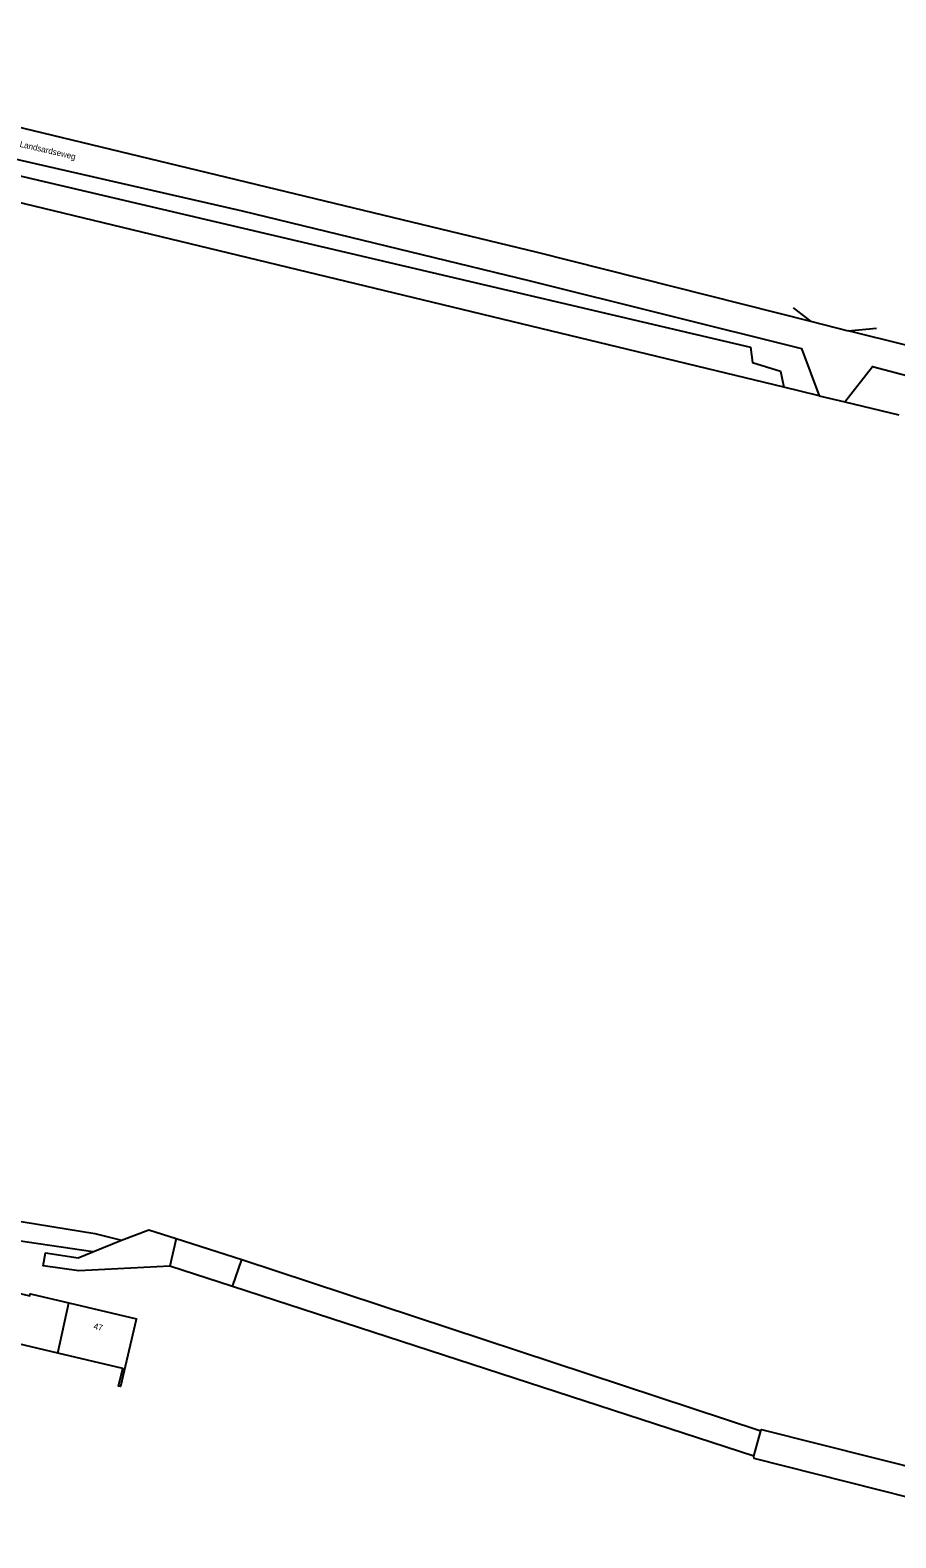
# Model space of a CAD drawing. Extents: x 152881 to 155736, y 382924 to 386919.
# Drawn here: x 154140.3 to 154283.4, y 385925 to 386174.3 of the extents above; entities that cross this region are included whole.
import ezdxf

# ---------------------------------------------------------------- set-up
doc = ezdxf.new("R2010")
doc.units = 0
for name, color, linetype in [('IMGEO_Berm_groen', 7, 'Continuous'), ('IMGEO_Gemengd_bos', 7, 'Continuous'), ('IMGEO_Groenvoorziening', 7, 'Continuous'), ('IMGEO_Hek', 7, 'Continuous'), ('IMGEO_Openbare_ruimte_label', 7, 'Continuous'), ('IMGEO_Pand', 7, 'Continuous'), ('IMGEO_Pand_nummerreeks', 7, 'Continuous'), ('IMGEO_Rijbaan_lokaal_gesloten', 7, 'Continuous'), ('IMGEO_Rijbaan_lokaal_halfverhard', 7, 'Continuous'), ('IMGEO_Rijbaan_lokaal_open', 7, 'Continuous')]:
    doc.layers.add(name, color=color, linetype=linetype)

msp = doc.modelspace()

# ---------------------------------------------------------------- linework, layer by layer
at = {"layer": 'IMGEO_Berm_groen'}
msp.add_lwpolyline([(154274.93, 386112.85), (154283.85, 386110.7)], dxfattribs=at)
at = {"layer": 'IMGEO_Gemengd_bos'}
for points in [[(154033.83, 386134.76), (154047.83, 386149.98), (154055.73, 386165.2), (154056.16, 386165.86), (154056.69, 386166.45), (154057.3, 386166.96), (154057.98, 386167.36), (154058.71, 386167.66), (154059.92, 386167.9), (154127.3, 386152.88), (154259.36, 386121.88), (154259.71, 386119.35), (154264.33, 386117.92), (154264.88, 386115.29)], [(154264.88, 386115.29), (154062.18, 386164.23), (154057.46, 386165.37), (154048.47, 386132.65), (154038.47, 386128.14)]]:
    msp.add_lwpolyline(points, dxfattribs=at)
at = {"layer": 'IMGEO_Groenvoorziening'}
for points in [[(154266.41, 386128.41), (154269.29, 386126.19)], [(154275.49, 386124.62), (154280.19, 386125.06)], [(154270.73, 386113.87), (154264.88, 386115.29)]]:
    msp.add_lwpolyline(points, dxfattribs=at)
at = {"layer": 'IMGEO_Hek'}
msp.add_lwpolyline([(154164.45, 385974.54), (154163.41, 385969.97)], dxfattribs=at)
at = {"layer": 'IMGEO_Pand'}
for points in [[(154144.86, 385955.57), (154138.4, 385957.1), (154138.46, 385957.34), (154126.96, 385960.07), (154128.11, 385964.85), (154128.94, 385968.34), (154129.35, 385968.26), (154129.23, 385967.65), (154140.25, 385965.04), (154140.32, 385965.39), (154140.59, 385965.33), (154146.72, 385963.88)], [(154146.72, 385963.88), (154157.86, 385961.26), (154157.83, 385961.14), (154155.22, 385950.04), (154154.93, 385950.11), (154155.61, 385953.03), (154144.86, 385955.57)], [(154144.86, 385955.57), (154146.72, 385963.88)]]:
    msp.add_lwpolyline(points, dxfattribs=at)
at = {"layer": 'IMGEO_Rijbaan_lokaal_gesloten'}
for points in [[(154088.55, 385992.5), (154127.33, 385979.3), (154129.62, 385978.83), (154151.01, 385975.37), (154155.39, 385974.23)], [(154150.69, 385972.31), (154129.28, 385975.47), (154126.33, 385976.28), (154121.26, 385978.08)], [(154150.69, 385972.31), (154155.39, 385974.23)]]:
    msp.add_lwpolyline(points, dxfattribs=at)
at = {"layer": 'IMGEO_Rijbaan_lokaal_halfverhard'}
for points in [[(153787.73, 386243.9), (153832.39, 386229.81), (153861.29, 386221.97), (153898.8, 386212.97), (153911.96, 386210.24), (153966.93, 386196.58), (153980.85, 386192.92), (153991.44, 386190.83), (154000, 386188.89), (154053.94, 386176.66), (154067.49, 386174.38), (154093.57, 386168.66), (154129.58, 386160.43), (154224.08, 386137.58), (154269.29, 386126.19)], [(154062.51, 386169.86), (154062.81, 386169.79), (154128.09, 386155.22), (154175.35, 386144.46), (154222.94, 386132.87), (154267.81, 386121.67), (154270.73, 386113.87)], [(154269.29, 386126.19), (154275.49, 386124.62)], [(154348.81, 386105.67), (154285.28, 386122.16), (154275.49, 386124.62)], [(154274.93, 386112.85), (154279.53, 386118.71), (154347.48, 386100.73), (154408.56, 386087.31), (154423.72, 386083.48), (154433.26, 386079.82)], [(154270.73, 386113.87), (154274.93, 386112.85)]]:
    msp.add_lwpolyline(points, dxfattribs=at)
at = {"layer": 'IMGEO_Rijbaan_lokaal_open'}
for points in [[(154155.39, 385974.23), (154159.91, 385975.98), (154164.45, 385974.54)], [(154163.41, 385969.97), (154148.33, 385969.16), (154142.44, 385970.02), (154142.85, 385972.13), (154148.24, 385971.33), (154150.69, 385972.31)], [(154164.45, 385974.54), (154163.41, 385969.97)], [(154164.45, 385974.54), (154175.28, 385971.08)], [(154173.77, 385966.59), (154163.41, 385969.97)], [(154173.77, 385966.59), (154175.28, 385971.08)], [(154175.28, 385971.08), (154261.09, 385942.7)], [(154259.92, 385938.51), (154173.77, 385966.59)], [(154259.92, 385938.51), (154261.09, 385942.7)], [(154261.09, 385942.7), (154261.16, 385942.95), (154307.85, 385931.18), (154311.09, 385928.75)], [(154308.18, 385925.03), (154306.17, 385926.49), (154259.97, 385938.16), (154259.92, 385938.51)]]:
    msp.add_lwpolyline(points, dxfattribs=at)

# ---------------------------------------------------------------- texts
at = {"layer": 'IMGEO_Openbare_ruimte_label'}
msp.add_text('Landsardseweg', height=1, rotation=346.8251, dxfattribs=at).set_placement((154138.52, 386155.03))
at = {"layer": 'IMGEO_Pand_nummerreeks'}
msp.add_text('47', height=1, rotation=346.7375, dxfattribs=at).set_placement((154150.73, 385959.57))

doc.saveas('drawing.dxf')
